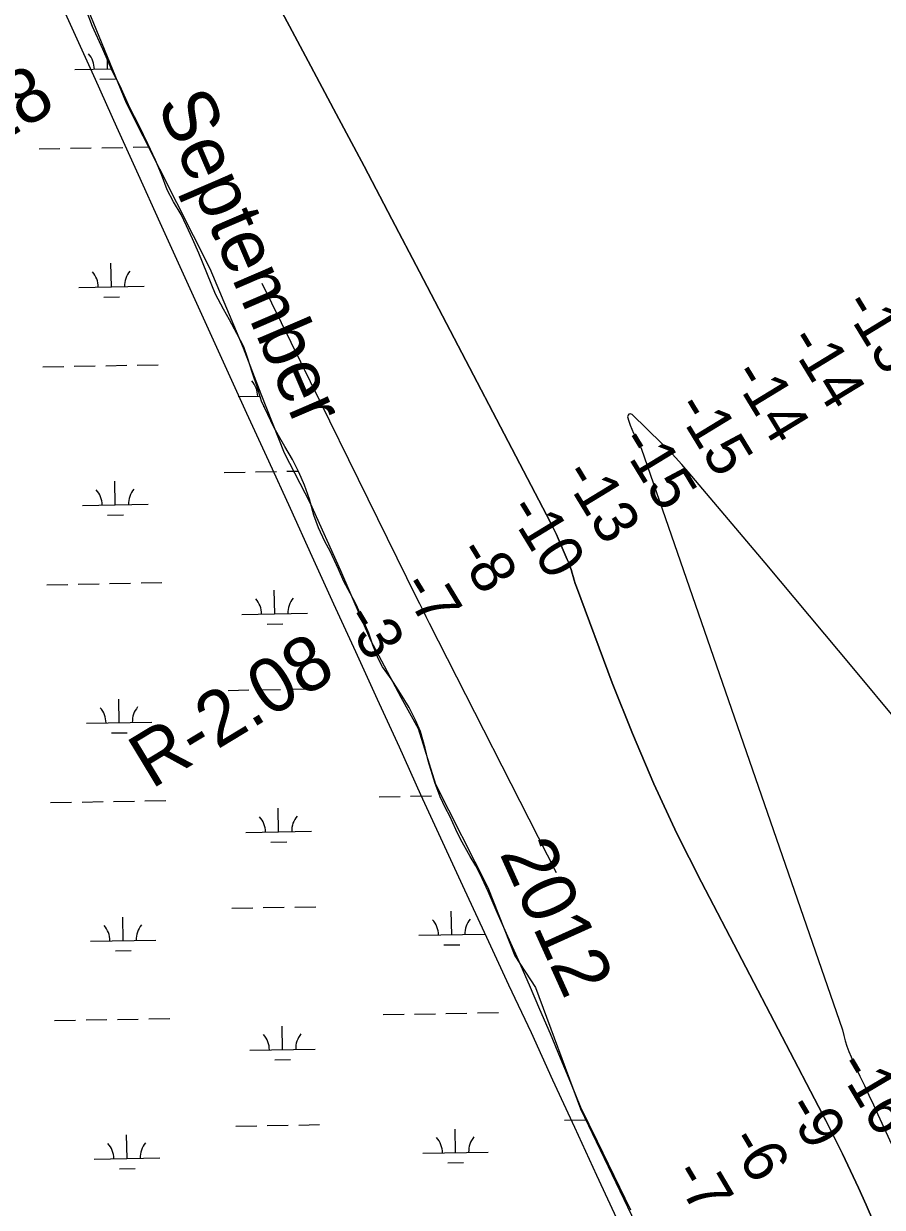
# Model space of a CAD drawing. Extents: x 3914892 to 3953151, y 242587 to 268572.
# Drawn here: x 3938240 to 3939552, y 251180 to 252987 of the extents above; entities that cross this region are included whole.
import ezdxf

# ---------------------------------------------------------------- set-up
doc = ezdxf.new("R2010")
doc.units = 0
for name, color, linetype in [('V-RIVR-EDGE', 7, 'Continuous'), ('V-RIVR-IDEN', 7, 'Continuous'), ('V-RIVR-RANG', 7, 'Continuous'), ('V-RIVR-RANG-IDEN', 7, 'Continuous'), ('V-RRAP-FSHR', 7, 'Continuous'), ('V-TOPO-DPTH', 7, 'Continuous'), ('V-TOPO-MINR', 7, 'Continuous'), ('V-WETL-SWMP', 7, 'Continuous')]:
    doc.layers.add(name, color=color, linetype=linetype)

msp = doc.modelspace()

# ---------------------------------------------------------------- linework, layer by layer
at = {"layer": 'V-RIVR-EDGE'}
msp.add_lwpolyline([(3938334.2, 253018.2), (3938396.7, 252865.6), (3938524.6, 252612.8), (3938575.8, 252492), (3938602.4, 252421.4), (3938638.3, 252331.3), (3938678.2, 252254.5), (3938724.3, 252152.1), (3938770.3, 252045.7), (3938816.4, 251958.6), (3938843, 251910.5), (3938869.6, 251825.6), (3938949.5, 251667.9), (3938990.4, 251563.5), (3939022.2, 251515.4), (3939090.7, 251330.1), (3939174.7, 251155)], dxfattribs=at)
at = {"layer": 'V-RRAP-FSHR'}
msp.add_lwpolyline([(3939149.6, 251155.9), (3939115.8, 251228.4), (3939082.2, 251301.6), (3939048.7, 251373.7), (3939015.8, 251446.3), (3938981.5, 251518.9), (3938947.9, 251591.5), (3938914.3, 251664.1), (3938880.7, 251736.7), (3938847.2, 251809.4), (3938814.2, 251882.1), (3938780.8, 251954.9), (3938747.6, 252027.7), (3938714.3, 252100.5), (3938681.1, 252173.2), (3938647.9, 252246.6), (3938614.7, 252318.8), (3938581.4, 252391.6), (3938548.2, 252464.3), (3938515, 252537.1), (3938481.8, 252609.9), (3938448.8, 252682.8), (3938415.8, 252755.6), (3938382.8, 252828.5), (3938349.9, 252901.4), (3938316.9, 252974.3), (3938283.9, 253047.2)], dxfattribs=at)
at = {"layer": 'V-TOPO-DPTH'}
msp.add_lwpolyline([(3939538.2, 251157.5), (3939527, 251183.7), (3939515.4, 251209.7), (3939503.3, 251235.5), (3939490.9, 251261.2), (3939470.4, 251302.3), (3939467.9, 251307.2), (3939465.4, 251312.2), (3939462.9, 251317.1), (3939460.3, 251322.1), (3939275.4, 251675.9), (3939238.1, 251750.6), (3939202.7, 251826.1), (3939170.1, 251903), (3939139.4, 251980.6), (3939084.8, 252126.7), (3939082.9, 252132), (3939081.1, 252137.2), (3939079.5, 252142.5), (3939078, 252147.9), (3939076.4, 252153.2), (3939074.7, 252158.5), (3939072.8, 252163.7), (3939070.7, 252168.9), (3939056.8, 252200.9), (3939054, 252207), (3939051.2, 252213.1), (3939048.3, 252219.1), (3939045.2, 252225), (3938844.8, 252607.9), (3938802.6, 252688.4), (3938760.3, 252768.8), (3938717.7, 252849), (3938675, 252929.3), (3938614.3, 253043.1)], dxfattribs=at)
at = {"layer": 'V-TOPO-MINR'}
for points in [[(3938614.3, 253043.1), (3938675, 252929.3), (3938717.7, 252849), (3938760.3, 252768.8), (3938802.6, 252688.4), (3938844.8, 252607.9), (3939045.2, 252225), (3939048.3, 252219.1), (3939051.2, 252213.1), (3939054, 252207), (3939056.8, 252200.9), (3939070.7, 252168.9), (3939072.8, 252163.7), (3939074.7, 252158.5), (3939076.4, 252153.2), (3939078, 252147.9), (3939079.5, 252142.5), (3939081.1, 252137.2), (3939082.9, 252132), (3939084.8, 252126.7), (3939139.4, 251980.6), (3939170.1, 251903), (3939202.7, 251826.1), (3939238.1, 251750.6), (3939275.4, 251675.9), (3939460.3, 251322.1), (3939462.9, 251317.1), (3939465.4, 251312.2), (3939467.9, 251307.2), (3939470.4, 251302.3), (3939490.9, 251261.2), (3939503.3, 251235.5), (3939515.4, 251209.7), (3939527, 251183.7), (3939538.2, 251157.5)], [(3938604.1, 252590.7), (3938839.9, 252111.3), (3938844.8, 252101.3), (3938849.8, 252091.4), (3938854.8, 252081.4), (3938859.8, 252071.5), (3939053.9, 251690.9)], [(3939575.9, 251920.3), (3939508.5, 252001.7), (3939440.8, 252082.8), (3939372.8, 252163.7), (3939255.4, 252302.6), (3939245.7, 252313.7), (3939235.8, 252324.6), (3939225.6, 252335.3), (3939215.2, 252345.7), (3939169.5, 252390.1), (3939166.8, 252390.9), (3939164.8, 252390.7), (3939163.5, 252389), (3939162.8, 252386.3), (3939164.5, 252379.9), (3939166.6, 252373.5), (3939169.1, 252367.4), (3939171.9, 252361.3), (3939183.5, 252338.6), (3939491.2, 251450.5), (3939492.9, 251442.1), (3939495.2, 251433.9), (3939497.8, 251425.7), (3939500.8, 251417.6), (3939504, 251409.6), (3939507.4, 251401.8), (3939511, 251393.9), (3939517.5, 251380.2), (3939524.4, 251365.5), (3939531.2, 251350.9), (3939538.1, 251336.2), (3939544.9, 251321.5), (3939752.9, 250871.3)]]:
    msp.add_lwpolyline(points, dxfattribs=at)
at = {"layer": 'V-WETL-SWMP'}
for p, q in [((3938345.6, 252982.3), (3938335.6, 253007.6)), ((3938361.1, 252947.7), (3938345.6, 252982.3)), ((3938376, 252913.7), (3938361.1, 252947.7)), ((3938318.4, 252916.5), (3938374.3, 252917.5)), ((3938368.4, 252917.4), (3938368.2, 252931.5)), ((3938356.7, 252901.7), (3938380.7, 252902.2)), ((3938387.6, 252891), (3938376, 252913.7)), ((3938402.7, 252858), (3938387.6, 252891)), ((3938416.6, 252830.4), (3938402.7, 252858)), ((3938429.8, 252802.9), (3938416.6, 252830.4)), ((3938263.8, 252795.4), (3938295.8, 252796)), ((3938311.7, 252796.3), (3938343.7, 252796.9)), ((3938359.7, 252797.1), (3938391.7, 252797.7)), ((3938407.7, 252798), (3938431.9, 252798.4)), ((3938441.5, 252778.2), (3938429.8, 252802.9)), ((3938450.8, 252756.1), (3938441.5, 252778.2)), ((3938459.5, 252733), (3938450.8, 252756.1)), ((3938469.2, 252714.7), (3938459.5, 252733)), ((3938480.8, 252695.5), (3938469.2, 252714.7)), ((3938489.2, 252678.2), (3938480.8, 252695.5)), ((3938498.2, 252658.3), (3938489.2, 252678.2)), ((3938507.9, 252636.5), (3938498.2, 252658.3)), ((3938533.4, 252573.7), (3938507.9, 252636.5)), ((3938374.4, 252584.8), (3938373.7, 252620.8)), ((3938324.4, 252583.9), (3938424.4, 252585.7)), ((3938545.4, 252550.6), (3938533.4, 252573.7)), ((3938362.7, 252569.1), (3938386.7, 252569.5)), ((3938554.7, 252534.6), (3938545.4, 252550.6)), ((3938566, 252513.8), (3938554.7, 252534.6)), ((3938576.7, 252493.3), (3938566, 252513.8)), ((3938582.5, 252475.6), (3938576.7, 252493.3)), ((3938269.7, 252462.8), (3938301.7, 252463.4)), ((3938317.7, 252463.7), (3938349.7, 252464.2)), ((3938365.7, 252464.5), (3938397.7, 252465.1)), ((3938413.7, 252465.4), (3938445.7, 252465.9)), ((3938589.3, 252454.8), (3938582.5, 252475.6)), ((3938597.4, 252430.7), (3938589.3, 252454.8)), ((3938603.5, 252410.2), (3938597.4, 252430.7)), ((3938567.9, 252417.4), (3938601.2, 252418)), ((3938622.7, 252370.6), (3938603.5, 252410.2)), ((3938606.2, 252402.6), (3938607.2, 252402.7)), ((3938629.8, 252357.9), (3938622.7, 252370.6)), ((3938639.1, 252340.9), (3938629.8, 252357.9)), ((3938651, 252321.3), (3938639.1, 252340.9)), ((3938660.7, 252302.1), (3938651, 252321.3)), ((3938546.5, 252301.6), (3938578.5, 252302.1)), ((3938594.5, 252302.4), (3938626.5, 252303)), ((3938642.5, 252303.3), (3938660, 252303.6)), ((3938669.4, 252281.9), (3938660.7, 252302.1)), ((3938380.3, 252252.1), (3938379.7, 252288.1)), ((3938676.9, 252260.8), (3938669.4, 252281.9)), ((3938330.3, 252251.2), (3938430.3, 252253)), ((3938683.3, 252236.1), (3938676.9, 252260.8)), ((3938368.6, 252236.5), (3938392.6, 252236.9)), ((3938690.5, 252217.2), (3938683.3, 252236.1)), ((3938700.5, 252196), (3938690.5, 252217.2)), ((3938708.5, 252181.3), (3938700.5, 252196)), ((3938721.4, 252153.7), (3938708.5, 252181.3)), ((3938729.5, 252135.1), (3938721.4, 252153.7)), ((3938275.7, 252130.2), (3938307.7, 252130.7)), ((3938323.7, 252131), (3938355.6, 252131.6)), ((3938371.6, 252131.9), (3938403.6, 252132.5)), ((3938419.6, 252132.8), (3938451.6, 252133.3)), ((3938623.8, 252085.7), (3938623.2, 252121.7)), ((3938739.2, 252117.2), (3938729.5, 252135.1)), ((3938747.6, 252101.2), (3938739.2, 252117.2)), ((3938573.8, 252084.8), (3938673.8, 252086.6)), ((3938757.6, 252079.7), (3938747.6, 252101.2)), ((3938612.1, 252070), (3938636.1, 252070.4)), ((3938767.3, 252056), (3938757.6, 252079.7)), ((3938773.7, 252038), (3938767.3, 252056)), ((3938781.8, 252017.5), (3938773.7, 252038)), ((3938788.6, 252005), (3938781.8, 252017.5)), ((3938801.8, 251986.7), (3938788.6, 252005)), ((3938815.9, 251964.3), (3938801.8, 251986.7)), ((3938552.5, 251968.9), (3938584.5, 251969.5)), ((3938600.5, 251969.8), (3938632.5, 251970.4)), ((3938648.5, 251970.6), (3938680.5, 251971.2)), ((3938829.2, 251942.5), (3938815.9, 251964.3)), ((3938386.3, 251919.5), (3938385.6, 251955.5)), ((3938838.8, 251923.3), (3938829.2, 251942.5)), ((3938846.6, 251906.3), (3938838.8, 251923.3)), ((3938336.3, 251918.6), (3938436.3, 251920.4)), ((3938374.6, 251903.9), (3938398.6, 251904.3)), ((3938853.7, 251880.7), (3938846.6, 251906.3)), ((3938858.3, 251861.4), (3938853.7, 251880.7)), ((3938868.9, 251826.8), (3938858.3, 251861.4)), ((3938876.7, 251806.6), (3938868.9, 251826.8)), ((3938281.6, 251797.6), (3938313.6, 251798.1)), ((3938329.6, 251798.4), (3938361.6, 251799)), ((3938377.6, 251799.3), (3938409.6, 251799.8)), ((3938425.6, 251800.1), (3938457.6, 251800.7)), ((3938783.4, 251806.5), (3938815.4, 251807.1)), ((3938831.4, 251807.4), (3938863.4, 251808)), ((3938884.8, 251789.3), (3938876.7, 251806.6)), ((3938629.8, 251753), (3938629.1, 251789)), ((3938891.2, 251776.8), (3938884.8, 251789.3)), ((3938900.6, 251756.6), (3938891.2, 251776.8)), ((3938579.8, 251752.1), (3938679.8, 251753.9)), ((3938907.7, 251741.5), (3938900.6, 251756.6)), ((3938922.5, 251715.3), (3938907.7, 251741.5)), ((3938618.1, 251737.4), (3938642.1, 251737.8)), ((3938930.9, 251700.9), (3938922.5, 251715.3)), ((3938940.5, 251681.6), (3938930.9, 251700.9)), ((3938949.9, 251661.8), (3938940.5, 251681.6)), ((3938963.5, 251629.8), (3938949.9, 251661.8)), ((3938558.4, 251636.3), (3938590.4, 251636.9)), ((3938606.4, 251637.2), (3938638.4, 251637.7)), ((3938654.4, 251638), (3938686.4, 251638.6)), ((3938392.2, 251586.9), (3938391.6, 251622.9)), ((3938894.1, 251595.9), (3938893.4, 251631.9)), ((3938980.1, 251593.1), (3938963.5, 251629.8)), ((3938844.1, 251595), (3938944.1, 251596.8)), ((3938342.2, 251586), (3938442.2, 251587.8)), ((3938882.3, 251580.2), (3938906.3, 251580.7)), ((3938996.6, 251556.1), (3938980.1, 251593.1)), ((3938380.5, 251571.3), (3938404.5, 251571.7)), ((3939012.8, 251519.1), (3938996.6, 251556.1)), ((3939028.9, 251481.9), (3939012.8, 251519.1)), ((3938789.4, 251473.9), (3938821.4, 251474.5)), ((3938837.4, 251474.8), (3938869.4, 251475.3)), ((3938885.4, 251475.6), (3938917.4, 251476.2)), ((3938933.4, 251476.5), (3938965.4, 251477.1)), ((3939044.8, 251444.7), (3939028.9, 251481.9)), ((3938287.6, 251464.9), (3938319.6, 251465.5)), ((3938335.6, 251465.8), (3938367.5, 251466.4)), ((3938383.5, 251466.7), (3938415.5, 251467.2)), ((3938431.5, 251467.5), (3938463.5, 251468.1)), ((3938635.7, 251420.4), (3938635.1, 251456.4)), ((3939060.4, 251407.3), (3939044.8, 251444.7)), ((3938585.7, 251419.5), (3938685.7, 251421.3)), ((3938624, 251404.8), (3938648, 251405.2)), ((3939075.9, 251369.9), (3939060.4, 251407.3)), ((3939091.2, 251332.4), (3939075.9, 251369.9)), ((3939117, 251280.1), (3939091.2, 251332.4)), ((3939066.2, 251312.7), (3939098.2, 251313.2)), ((3938398.2, 251254.3), (3938397.5, 251290.3)), ((3938564.4, 251303.7), (3938596.4, 251304.3)), ((3938612.4, 251304.5), (3938644.4, 251305.1)), ((3938660.4, 251305.4), (3938692.4, 251306)), ((3938900, 251263.3), (3938899.4, 251299.2)), ((3939142.5, 251227.7), (3939117, 251280.1)), ((3938348.2, 251253.4), (3938448.2, 251255.2)), ((3938850, 251262.4), (3938950, 251264.1)), ((3938386.5, 251238.6), (3938410.5, 251239.1)), ((3938888.3, 251247.6), (3938912.3, 251248)), ((3939167.9, 251175.2), (3939142.5, 251227.7))]:
    msp.add_line(p, q, dxfattribs=at)
for centre, start, end in [((3938313.2, 252916.9), 0.2532, 41.7968), ((3938429.6, 252586.2), 140.2532, 181.7968), ((3938319.1, 252584.2), 0.2532, 41.7968), ((3938562.6, 252417.8), 0.2532, 41.7968), ((3938325.1, 252251.6), 0.2532, 41.7968), ((3938435.6, 252253.6), 140.2532, 181.7968), ((3938568.6, 252085.1), 0.2532, 41.7968), ((3938679.1, 252087.1), 140.2532, 181.7968), ((3938331, 251919), 0.2532, 41.7968), ((3938441.5, 251921), 140.2532, 181.7968), ((3938685, 251754.5), 140.2532, 181.7968), ((3938574.5, 251752.5), 0.2532, 41.7968), ((3938838.8, 251595.4), 0.2532, 41.7968), ((3938949.3, 251597.3), 140.2532, 181.7968), ((3938337, 251586.4), 0.2532, 41.7968), ((3938447.5, 251588.4), 140.2532, 181.7968), ((3938580.5, 251419.9), 0.2532, 41.7968), ((3938691, 251421.9), 140.2532, 181.7968), ((3938342.9, 251253.8), 0.2532, 41.7968), ((3938453.4, 251255.7), 140.2532, 181.7968), ((3938844.8, 251262.7), 0.2532, 41.7968), ((3938955.2, 251264.7), 140.2532, 181.7968)]:
    msp.add_arc(centre, 35.2, start, end, dxfattribs=at)

# ---------------------------------------------------------------- texts
at = {"layer": 'V-RIVR-IDEN'}
for s, rotation, p in [('September', 293.2777, (3938443.3, 252864.2)), ('2012', 294.2818, (3938966.6, 251720))]:
    msp.add_text(s, height=83, rotation=rotation, dxfattribs=at).set_placement(p)
at = {"layer": 'V-RIVR-RANG'}
for s, rotation, p in [('-13', 301.3319, (3939489.4, 252557.5)), ('-14', 301.3319, (3939405.6, 252502.8)), ('-14', 301.3319, (3939320.1, 252451)), ('-15', 301.3319, (3939233.6, 252400.8)), ('-15', 301.3319, (3939148, 252349)), ('-13', 301.3319, (3939061.7, 252298.5)), ('-10', 301.3319, (3938977.4, 252244.7)), ('-8', 301.3319, (3938899.9, 252179.6)), ('-7', 301.3319, (3938814.5, 252127.6)), ('-3', 301.0483, (3938727.6, 252078.6)), ('-16', 300.5869, (3939480.4, 251395.8)), ('-9', 300.5869, (3939402.1, 251331.8)), ('-6', 300.5869, (3939315.7, 251281.3)), ('-7', 300.5869, (3939229.4, 251230.9))]:
    msp.add_text(s, height=67, rotation=rotation, dxfattribs=at).set_placement(p)
at = {"layer": 'V-RIVR-RANG-IDEN'}
for s, rotation, p in [('R-2.28', 31.6784, (3938009.5, 252683)), ('R-2.08', 31.1903, (3938435.6, 251817.4))]:
    msp.add_text(s, height=83, rotation=rotation, dxfattribs=at).set_placement(p)

doc.saveas('drawing.dxf')
